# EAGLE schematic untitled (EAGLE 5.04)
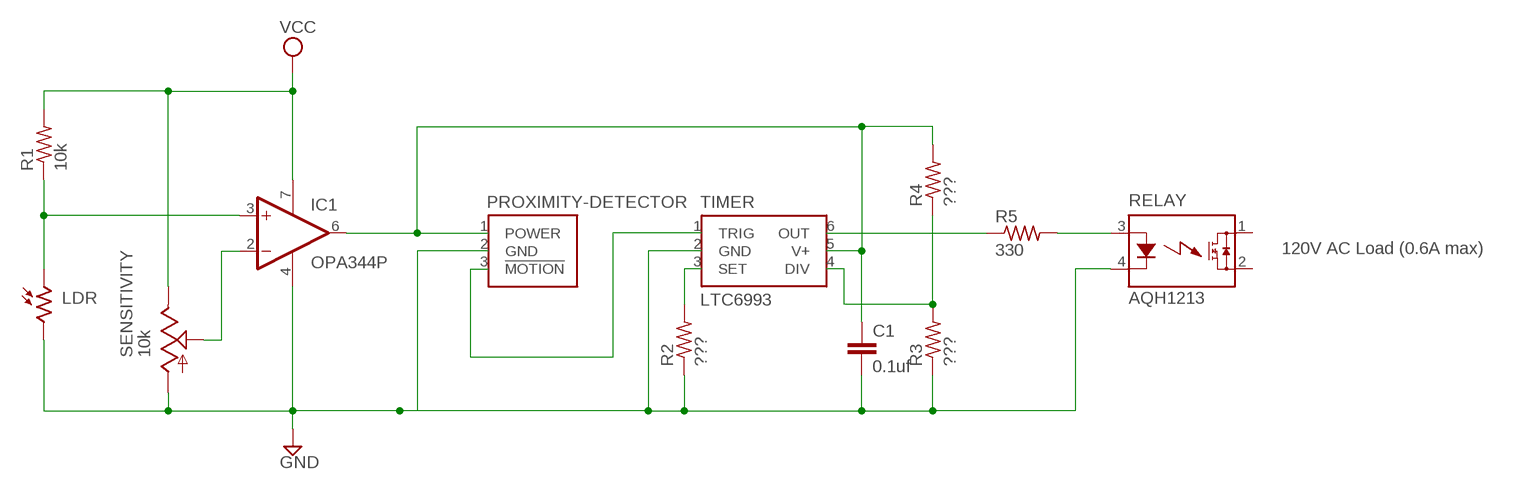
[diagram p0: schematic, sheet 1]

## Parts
C1  0.1uf  C-EU050-024X044  [C050-024X044]
IC1  OPA344P  [DIL08]
LDR  W5560_11  [W55XX]
PROXIMITY-DETECTOR  PROXIMITY-DETECTOR  [3SIL]
R1  10k  R-US_VMTA55  [VMTA55]
R2  ???  R-US_VMTA55  [VMTA55]
R3  ???  R-US_VMTA55  [VMTA55]
R4  ???  R-US_VMTA55  [VMTA55]
R5  330  R-US_VMTA55  [VMTA55]
RELAY  AQH1213  AQ1AD2-3  [AQ1]
SENSITIVITY  10k  TRIM_US-S64W  [S64W]
TIMER  LTC6993  [SOT-23-6]

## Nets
GND: C1.2 IC1.4(V-) LDR.2 PROXIMITY-DETECTOR.2(GND) R2.1 R3.1 RELAY.4(K) SENSITIVITY.A TIMER.2(GND)
N$1: IC1.2(-IN) SENSITIVITY.S
N$2: PROXIMITY-DETECTOR.3(!MOTION) TIMER.1(TRIG)
N$3: IC1.3(+IN) LDR.1 R1.1
N$5: R3.2 R4.1 TIMER.4(DIV)
N$6: C1.1 IC1.6(OUT) PROXIMITY-DETECTOR.1(POWER) R4.2 TIMER.5(V+)
N$7: R5.1 TIMER.6(OUT)
N$8: R2.2 TIMER.3(SET)
N$9: R5.2 RELAY.3(A)
VCC: IC1.7(V+) R1.2 SENSITIVITY.E
Unconnected: RELAY.1(DS1) RELAY.2(DS2)

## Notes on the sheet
- 120V AC Load (0.6A max)

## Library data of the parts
C1 = rcl:C-EU: CAPACITOR, European symbol
IC1 = linear:OPA*: Single Operational Amplifier Low Power, Single-Supply, Rail-To-Rail Operational Amplifier Source: http://focus.ti.com/lit/ds/symlink/opa2345.pdf
LDR = photo-elements:W55: Photo Sensor Oil Burner Control Applications
PROXIMITY-DETECTOR = trl:PROXIMITY-DETECTOR
R1-R5 = rcl:R-US_: RESISTOR, American symbol
RELAY = relay:AQ*: SOLID STATE RELAY NAiS Source: http://www.mew-europe.com/.. en_ds_61601_0000.pdf
SENSITIVITY = pot:TRIM_US-: POTENTIOMETER
TIMER = trl:LTC6993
